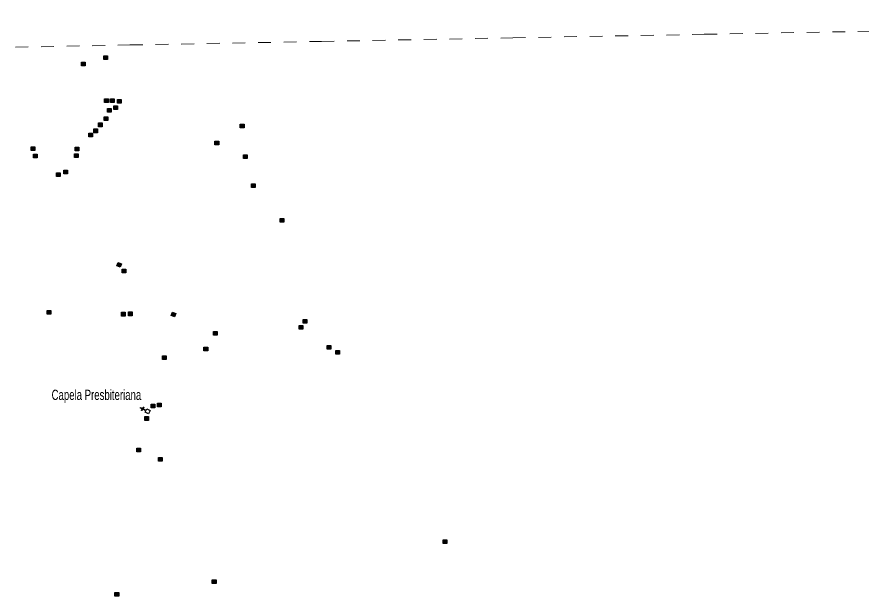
# Model space of a CAD drawing. Extents: x 220.8 to 246.7, y 7287.6 to 7315.8.
# Drawn here: x 233.32 to 239.91, y 7311.26 to 7315.78 of the extents above; entities that cross this region are included whole.
import ezdxf
from ezdxf.enums import TextEntityAlignment as Align

# ---------------------------------------------------------------- set-up
doc = ezdxf.new("R2010")
doc.units = 0
doc.header["$LTSCALE"] = 0.032
doc.linetypes.add('SHORT_DASHED', pattern=[2.7, 1.5, -1.2])
for name, color, linetype, lineweight in [('2', 7, 'Continuous', 25), ('58', 7, 'SHORT_DASHED', 13), ('6', 7, 'Continuous', 25)]:
    doc.layers.add(name, color=color, linetype=linetype, lineweight=lineweight)
doc.layers.add('61', color=7, linetype='Continuous')

msp = doc.modelspace()

# ---------------------------------------------------------------- hatches: boundary and pattern name
at = {"layer": '2'}
for points in [[(233.9957, 7315.4804), (234.0247, 7315.4804), (234.0247, 7315.4514), (233.9957, 7315.4514)], [(233.8204, 7315.429), (233.8494, 7315.429), (233.8494, 7315.4), (233.8204, 7315.4)], [(234.0019, 7315.1429), (234.0309, 7315.1429), (234.0309, 7315.1139), (234.0019, 7315.1139)], [(234.0467, 7315.1449), (234.0757, 7315.1449), (234.0757, 7315.1159), (234.0467, 7315.1159)], [(234.0732, 7315.0899), (234.1022, 7315.0899), (234.1022, 7315.0609), (234.0732, 7315.0609)], [(234.1017, 7315.1388), (234.1307, 7315.1388), (234.1307, 7315.1098), (234.1017, 7315.1098)], [(234.0243, 7315.0675), (234.0533, 7315.0675), (234.0533, 7315.0385), (234.0243, 7315.0385)], [(233.953, 7314.9554), (233.982, 7314.9554), (233.982, 7314.9264), (233.953, 7314.9264)], [(233.9978, 7315.0023), (234.0268, 7315.0023), (234.0268, 7314.9733), (233.9978, 7314.9733)], [(235.0606, 7314.9463), (235.0896, 7314.9463), (235.0896, 7314.9173), (235.0606, 7314.9173)], [(233.9183, 7314.9085), (233.9473, 7314.9085), (233.9473, 7314.8795), (233.9183, 7314.8795)], [(233.8775, 7314.8748), (233.9065, 7314.8748), (233.9065, 7314.8458), (233.8775, 7314.8458)], [(234.863, 7314.8139), (234.892, 7314.8139), (234.892, 7314.7849), (234.863, 7314.7849)], [(233.4279, 7314.7699), (233.4569, 7314.7699), (233.4569, 7314.7409), (233.4279, 7314.7409)], [(233.772, 7314.766), (233.801, 7314.766), (233.801, 7314.737), (233.772, 7314.737)], [(233.4475, 7314.7109), (233.4765, 7314.7109), (233.4765, 7314.6819), (233.4475, 7314.6819)], [(233.7661, 7314.7149), (233.7951, 7314.7149), (233.7951, 7314.6859), (233.7661, 7314.6859)], [(235.0851, 7314.7058), (235.1141, 7314.7058), (235.1141, 7314.6768), (235.0851, 7314.6768)], [(233.6265, 7314.5674), (233.6555, 7314.5674), (233.6555, 7314.5384), (233.6265, 7314.5384)], [(233.6835, 7314.5871), (233.7125, 7314.5871), (233.7125, 7314.5581), (233.6835, 7314.5581)], [(235.1486, 7314.4811), (235.1776, 7314.4811), (235.1776, 7314.4521), (235.1486, 7314.4521)], [(235.3726, 7314.211), (235.4016, 7314.211), (235.4016, 7314.182), (235.3726, 7314.182)], [(234.1068, 7313.867), (234.134, 7313.8572), (234.1242, 7313.8299), (234.0969, 7313.8397)], [(234.1381, 7313.8136), (234.1671, 7313.8136), (234.1671, 7313.7846), (234.1381, 7313.7846)], [(233.5541, 7313.4913), (233.5831, 7313.4913), (233.5831, 7313.4623), (233.5541, 7313.4623)], [(234.1326, 7313.4775), (234.1616, 7313.4775), (234.1616, 7313.4485), (234.1326, 7313.4485)], [(234.1877, 7313.4803), (234.2167, 7313.4803), (234.2167, 7313.4513), (234.1877, 7313.4513)], [(234.5308, 7313.479), (234.558, 7313.4691), (234.5481, 7313.4418), (234.5209, 7313.4517)], [(235.5204, 7313.3752), (235.5494, 7313.3752), (235.5494, 7313.3462), (235.5204, 7313.3462)], [(235.5515, 7313.4209), (235.5805, 7313.4209), (235.5805, 7313.3919), (235.5515, 7313.3919)], [(234.8504, 7313.3274), (234.8794, 7313.3274), (234.8794, 7313.2984), (234.8504, 7313.2984)], [(234.7773, 7313.2047), (234.8063, 7313.2047), (234.8063, 7313.1757), (234.7773, 7313.1757)], [(235.7382, 7313.2197), (235.7672, 7313.2197), (235.7672, 7313.1907), (235.7382, 7313.1907)], [(235.8066, 7313.1803), (235.8356, 7313.1803), (235.8356, 7313.1513), (235.8066, 7313.1513)], [(234.4539, 7313.1386), (234.4829, 7313.1386), (234.4829, 7313.1096), (234.4539, 7313.1096)], [(234.364, 7312.76), (234.393, 7312.76), (234.393, 7312.731), (234.364, 7312.731)], [(234.4136, 7312.7682), (234.4426, 7312.7682), (234.4426, 7312.7392), (234.4136, 7312.7392)], [(234.3144, 7312.6635), (234.3434, 7312.6635), (234.3434, 7312.6345), (234.3144, 7312.6345)], [(234.2537, 7312.4181), (234.2827, 7312.4181), (234.2827, 7312.3891), (234.2537, 7312.3891)], [(234.4219, 7312.3436), (234.4509, 7312.3436), (234.4509, 7312.3146), (234.4219, 7312.3146)], [(236.6431, 7311.7021), (236.6721, 7311.7021), (236.6721, 7311.6731), (236.6431, 7311.6731)], [(234.8423, 7311.3903), (234.8713, 7311.3903), (234.8713, 7311.3613), (234.8423, 7311.3613)], [(234.0827, 7311.2917), (234.1117, 7311.2917), (234.1117, 7311.2627), (234.0827, 7311.2627)]]:
    msp.add_hatch(color=256, dxfattribs=at).paths.add_polyline_path(points)

# ---------------------------------------------------------------- linework, layer by layer
for points in [[(233.9957, 7315.4804), (234.0247, 7315.4804), (234.0247, 7315.4514), (233.9957, 7315.4514)], [(233.8204, 7315.429), (233.8494, 7315.429), (233.8494, 7315.4), (233.8204, 7315.4)], [(234.0019, 7315.1429), (234.0309, 7315.1429), (234.0309, 7315.1139), (234.0019, 7315.1139)], [(234.0467, 7315.1449), (234.0757, 7315.1449), (234.0757, 7315.1159), (234.0467, 7315.1159)], [(234.0732, 7315.0899), (234.1022, 7315.0899), (234.1022, 7315.0609), (234.0732, 7315.0609)], [(234.1017, 7315.1388), (234.1307, 7315.1388), (234.1307, 7315.1098), (234.1017, 7315.1098)], [(234.0243, 7315.0675), (234.0533, 7315.0675), (234.0533, 7315.0385), (234.0243, 7315.0385)], [(233.953, 7314.9554), (233.982, 7314.9554), (233.982, 7314.9264), (233.953, 7314.9264)], [(233.9978, 7315.0023), (234.0268, 7315.0023), (234.0268, 7314.9733), (233.9978, 7314.9733)], [(235.0606, 7314.9463), (235.0896, 7314.9463), (235.0896, 7314.9173), (235.0606, 7314.9173)], [(233.9183, 7314.9085), (233.9473, 7314.9085), (233.9473, 7314.8795), (233.9183, 7314.8795)], [(233.8775, 7314.8748), (233.9065, 7314.8748), (233.9065, 7314.8458), (233.8775, 7314.8458)], [(234.863, 7314.8139), (234.892, 7314.8139), (234.892, 7314.7849), (234.863, 7314.7849)], [(233.4279, 7314.7699), (233.4569, 7314.7699), (233.4569, 7314.7409), (233.4279, 7314.7409)], [(233.772, 7314.766), (233.801, 7314.766), (233.801, 7314.737), (233.772, 7314.737)], [(233.4475, 7314.7109), (233.4765, 7314.7109), (233.4765, 7314.6819), (233.4475, 7314.6819)], [(233.7661, 7314.7149), (233.7951, 7314.7149), (233.7951, 7314.6859), (233.7661, 7314.6859)], [(235.0851, 7314.7058), (235.1141, 7314.7058), (235.1141, 7314.6768), (235.0851, 7314.6768)], [(233.6265, 7314.5674), (233.6555, 7314.5674), (233.6555, 7314.5384), (233.6265, 7314.5384)], [(233.6835, 7314.5871), (233.7125, 7314.5871), (233.7125, 7314.5581), (233.6835, 7314.5581)], [(235.1486, 7314.4811), (235.1776, 7314.4811), (235.1776, 7314.4521), (235.1486, 7314.4521)], [(235.3726, 7314.211), (235.4016, 7314.211), (235.4016, 7314.182), (235.3726, 7314.182)], [(234.1068, 7313.867), (234.134, 7313.8572), (234.1242, 7313.8299), (234.0969, 7313.8397)], [(234.1381, 7313.8136), (234.1671, 7313.8136), (234.1671, 7313.7846), (234.1381, 7313.7846)], [(233.5541, 7313.4913), (233.5831, 7313.4913), (233.5831, 7313.4623), (233.5541, 7313.4623)], [(234.1326, 7313.4775), (234.1616, 7313.4775), (234.1616, 7313.4485), (234.1326, 7313.4485)], [(234.1877, 7313.4803), (234.2167, 7313.4803), (234.2167, 7313.4513), (234.1877, 7313.4513)], [(234.5308, 7313.479), (234.558, 7313.4691), (234.5481, 7313.4418), (234.5209, 7313.4517)], [(235.5204, 7313.3752), (235.5494, 7313.3752), (235.5494, 7313.3462), (235.5204, 7313.3462)], [(235.5515, 7313.4209), (235.5805, 7313.4209), (235.5805, 7313.3919), (235.5515, 7313.3919)], [(234.8504, 7313.3274), (234.8794, 7313.3274), (234.8794, 7313.2984), (234.8504, 7313.2984)], [(234.7773, 7313.2047), (234.8063, 7313.2047), (234.8063, 7313.1757), (234.7773, 7313.1757)], [(235.7382, 7313.2197), (235.7672, 7313.2197), (235.7672, 7313.1907), (235.7382, 7313.1907)], [(235.8066, 7313.1803), (235.8356, 7313.1803), (235.8356, 7313.1513), (235.8066, 7313.1513)], [(234.4539, 7313.1386), (234.4829, 7313.1386), (234.4829, 7313.1096), (234.4539, 7313.1096)], [(234.364, 7312.76), (234.393, 7312.76), (234.393, 7312.731), (234.364, 7312.731)], [(234.4136, 7312.7682), (234.4426, 7312.7682), (234.4426, 7312.7392), (234.4136, 7312.7392)], [(234.3144, 7312.6635), (234.3434, 7312.6635), (234.3434, 7312.6345), (234.3144, 7312.6345)], [(234.2537, 7312.4181), (234.2827, 7312.4181), (234.2827, 7312.3891), (234.2537, 7312.3891)], [(234.4219, 7312.3436), (234.4509, 7312.3436), (234.4509, 7312.3146), (234.4219, 7312.3146)], [(236.6431, 7311.7021), (236.6721, 7311.7021), (236.6721, 7311.6731), (236.6431, 7311.6731)], [(234.8423, 7311.3903), (234.8713, 7311.3903), (234.8713, 7311.3613), (234.8423, 7311.3613)], [(234.0827, 7311.2917), (234.1117, 7311.2917), (234.1117, 7311.2627), (234.0827, 7311.2627)]]:
    msp.add_lwpolyline(points, close=True, dxfattribs=at)
at = {"layer": '58'}
msp.add_lwpolyline([(220.7543, 7315.3049), (222.2482, 7315.3343), (223.7422, 7315.3636), (225.2361, 7315.3926), (226.7301, 7315.4216), (228.224, 7315.4503), (229.718, 7315.4789), (231.2119, 7315.5074), (232.7059, 7315.5357), (234.1998, 7315.5638), (235.6938, 7315.5918), (237.1877, 7315.6196), (238.6817, 7315.6472), (240.1757, 7315.6748), (241.6697, 7315.7021), (243.1636, 7315.7293), (244.6576, 7315.7563), (246.1516, 7315.7832)], dxfattribs=at)
at = {"layer": '6'}
for points in [[(234.324, 7312.7089), (234.2997, 7312.721), (234.2943, 7312.7102), (234.2899, 7312.7124), (234.2954, 7312.7232), (234.2807, 7312.7306), (234.2828, 7312.7349), (234.2975, 7312.7275), (234.3029, 7312.7383), (234.3073, 7312.7362), (234.3019, 7312.7253), (234.3261, 7312.7132)], [(234.3261, 7312.7132), (234.3315, 7312.724), (234.3575, 7312.7111), (234.3445, 7312.6851), (234.3186, 7312.6981), (234.324, 7312.7089)]]:
    msp.add_lwpolyline(points, dxfattribs=at)

# ---------------------------------------------------------------- texts
at = {"layer": '61', "width": 0.7}
msp.add_text('Capela Presbiteriana', height=0.08, dxfattribs=at).set_placement((234.2873, 7312.7935), align=Align.RIGHT)

doc.saveas('drawing.dxf')
